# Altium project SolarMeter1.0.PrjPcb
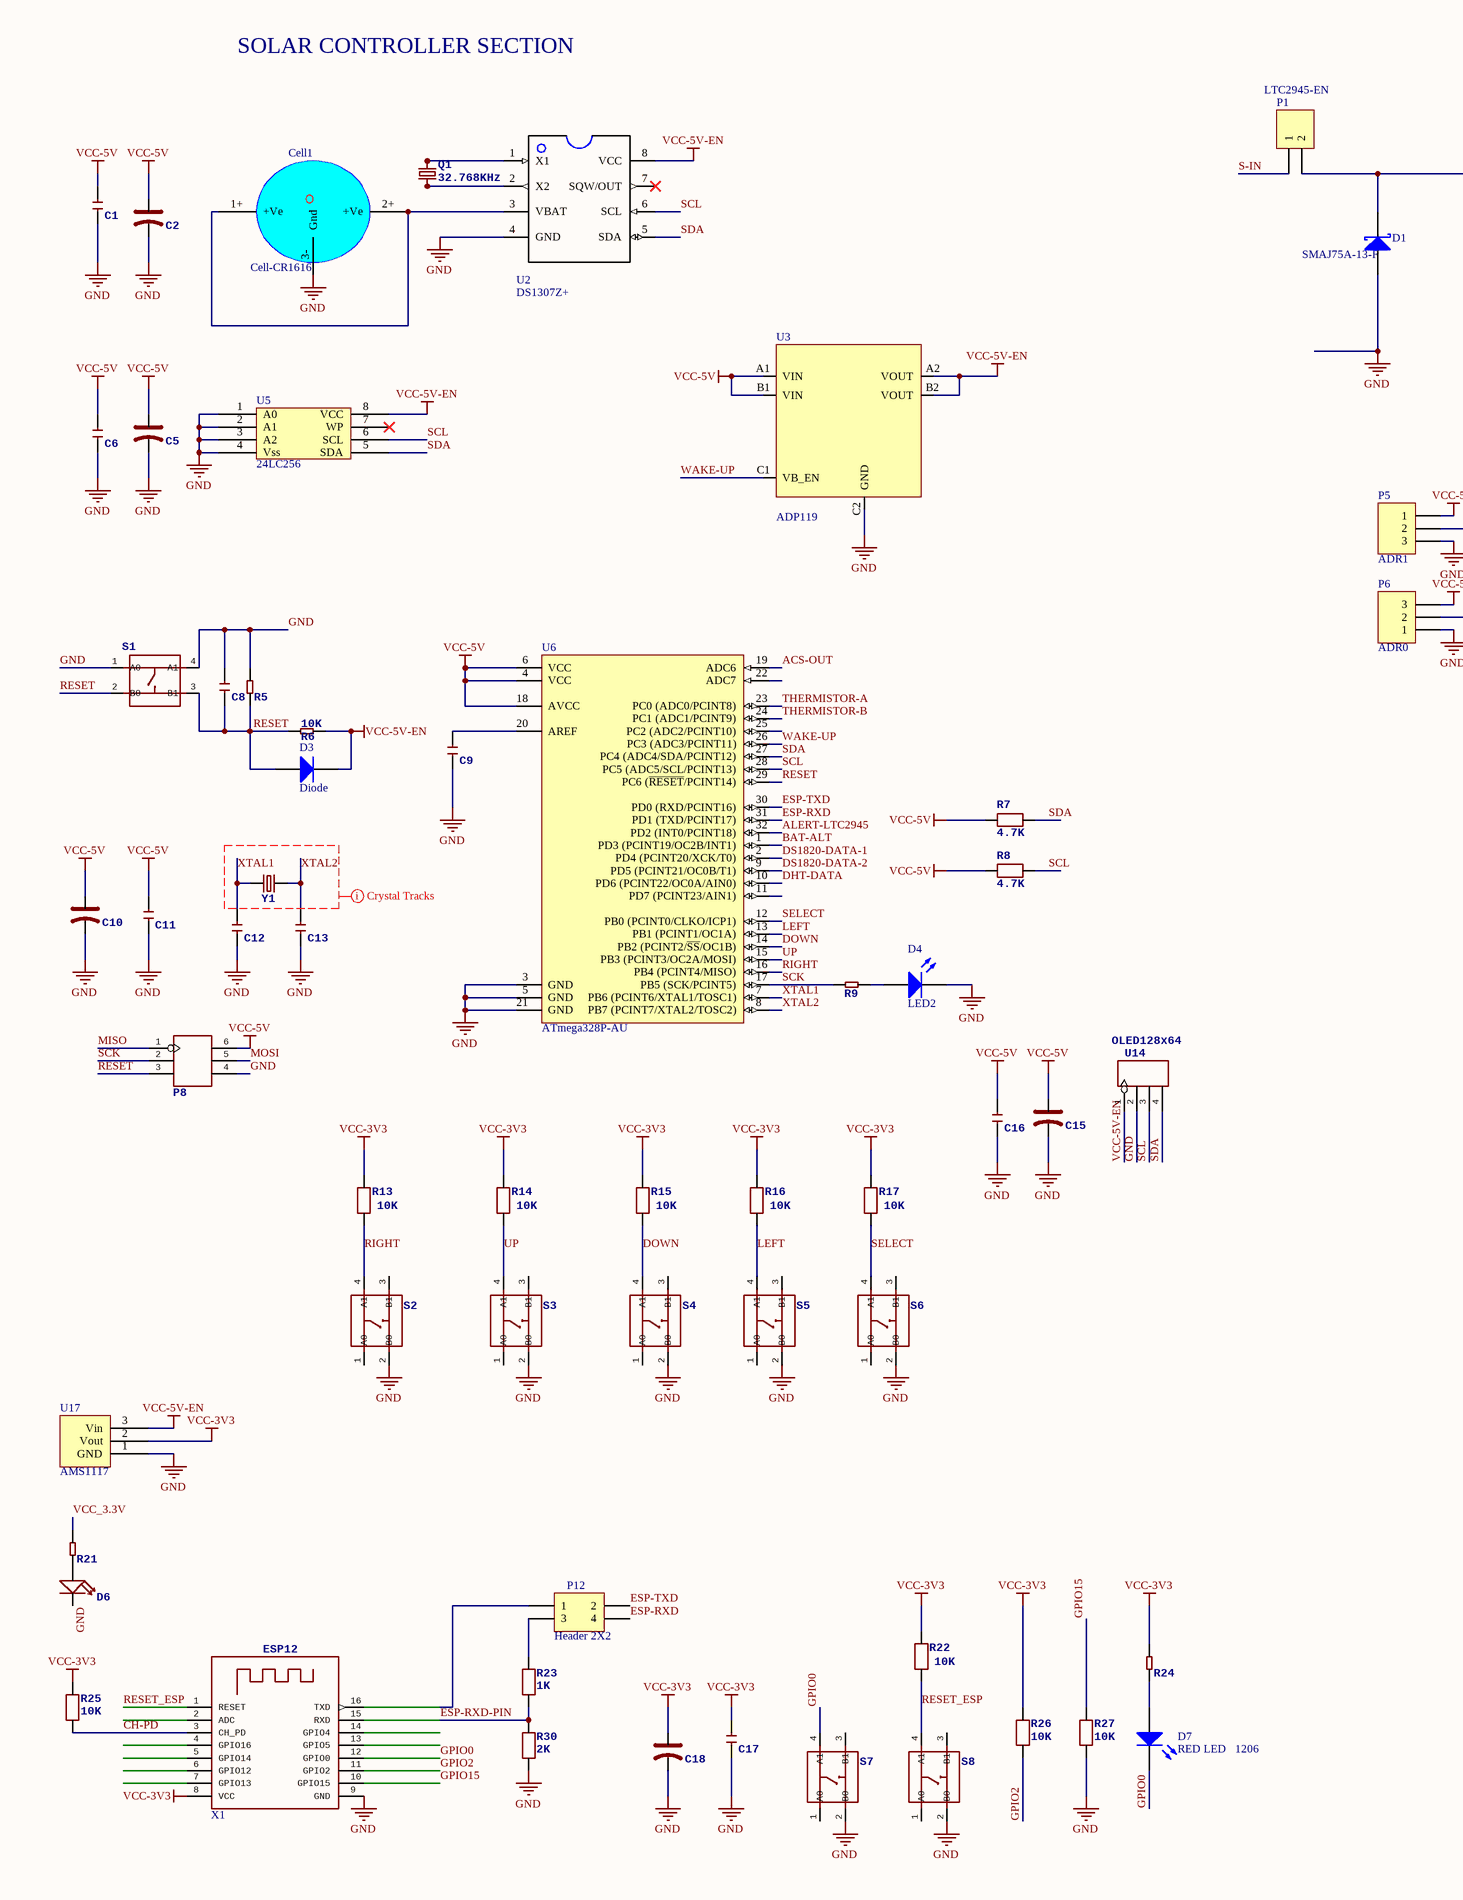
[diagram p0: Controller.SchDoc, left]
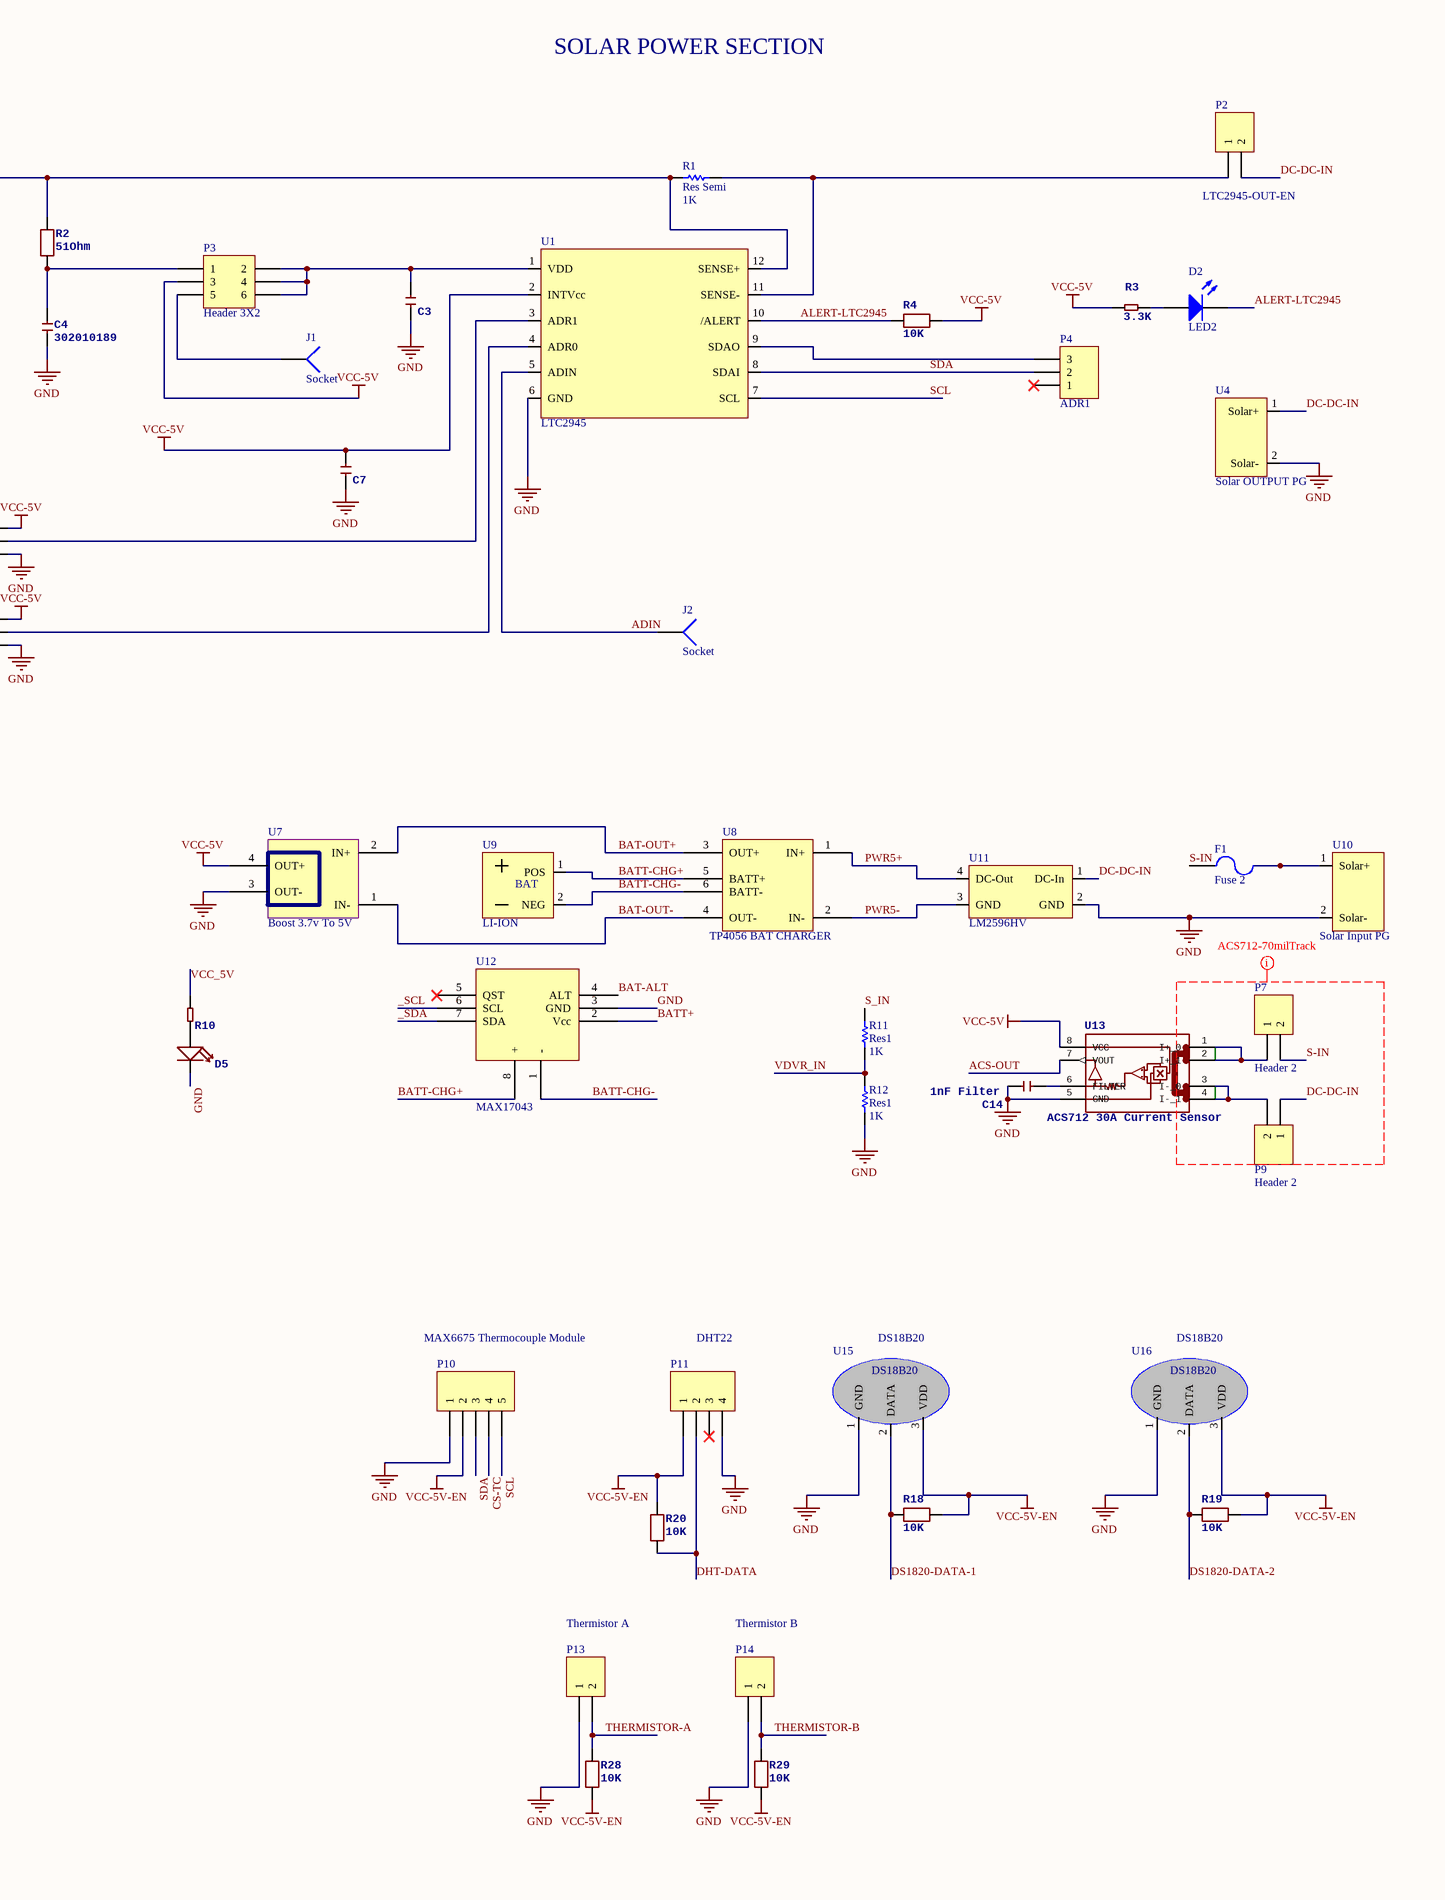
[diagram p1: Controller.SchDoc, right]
1 sheet, 101 parts. Net scope: global (net labels, ports and power ports of the same name join across sheets).
Board file: SolarMetering1.0.PcbDoc

## Sheet Controller.SchDoc: Solar Monitoring 1.0
size A2

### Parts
C1  302010165  [C0805]  (value not drawn)
C2  302020002  [AVX-A]  (value not drawn)
C3  302010165  [C0805]  (value not drawn)
C4  302010189  [C1206]
C5  302020002  [AVX-A]  (value not drawn)
C6  302010165  [C0805]  (value not drawn)
C7  302010165  [C0805]  (value not drawn)
C8  302010165  [C0805]  (value not drawn)
C9  302010165  [C0805]  (value not drawn)
C10  302020002  [AVX-A]  (value not drawn)
C11  302010165  [C0805]  (value not drawn)
C12  302010018  [C0805]  (value not drawn)
C13  302010018  [C0805]  (value not drawn)
C14  1nF Filter  [C0805]
C15  302020002  [AVX-A]  (value not drawn)
C16  302010165  [C0805]  (value not drawn)
C17  302010165  [C0805]  (value not drawn)
C18  302020002  [AVX-A]  (value not drawn)
Cell1  Cell-CR1616  [CellCR1616]
D1  SMAJ75A-13-F  [SMAJ5.0-TVS]
D2  LED2  [3.2X1.6X1.1]
D3  Diode  [1206 Diode SMD]
D4  LED2  [3.2X1.6X1.1]
D5  304090046  [LED-0805]  (value not drawn)
D6  304090045  [LED-0603]  (value not drawn)
D7  RED LED   1206  [3.2X1.6X1.1]
F1  Fuse 2  [PIN-W2/E2.8]
J1  Socket  [PIN1]
J2  Socket  [PIN1]
P1  LTC2945-EN  [HDR1X2]
P2  LTC2945-OUT-EN  [HDR1X2]
P3  Header 3X2  [HDR2X3]
P4  ADR1  [HDR1X3]
P5  ADR1  [HDR1X3]
P6  ADR0  [HDR1X3]
P7  Header 2  [HDR1X2]
P8  320020077  [HDR1X6]  (value not drawn)
P9  Header 2  [HDR1X2]
P10  MAX6675 Thermocouple Module  [HDR1X5]
P11  DHT22  [HDR1X4]
P12  Header 2X2  [HDR2X2]
P13  Thermistor A  [HDR1X2]
P14  Thermistor B  [HDR1X2]
Q1  32.768KHz  [RTC-XTAL]
R1  Res Semi  value 1K  [AXIAL-0.5]
R2  51Ohm  [R0805]
R3  3.3K  [C1206]
R4  10K  [R0805]
R5  301010006  [R0402]  (value not drawn)
R6  10K  [R0805]
R7  4.7K  [R0805]
R8  4.7K  [R0805]
R9  301010466  [C1206]  (value not drawn)
R10  301010006  [R0402]  (value not drawn)
R11  Res1  value 1K  [AXIAL-0.3]
R12  Res1  value 1K  [AXIAL-0.3]
R13  10K  [R0805]
R14  10K  [R0805]
R15  10K  [R0805]
R16  10K  [R0805]
R17  10K  [R0805]
R18  10K  [R0805]
R19  10K  [R0805]
R20  10K  [R0805]
R21  301010006  [R0402]  (value not drawn)
R22  10K  [R0805]
R23  1K  [R0805]
R24  1K  [C1206]  (value not drawn)
R25  10K  [R0805]
R26  10K  [R0805]
R27  10K  [R0805]
R28  10K  [R0805]
R29  10K  [R0805]
R30  2K  [R0805]
S1  311020004  [SW4-SMD-6.0X6.0X5.0MM]  (value not drawn)
S2  311020004  [SW4-SMD-6.0X6.0X5.0MM]  (value not drawn)
S3  311020004  [SW4-SMD-6.0X6.0X5.0MM]  (value not drawn)
S4  311020004  [SW4-SMD-6.0X6.0X5.0MM]  (value not drawn)
S5  311020004  [SW4-SMD-6.0X6.0X5.0MM]  (value not drawn)
S6  311020004  [SW4-SMD-6.0X6.0X5.0MM]  (value not drawn)
S7  311020004  [SW4-SMD-6.0X6.0X5.0MM]  (value not drawn)
S8  311020004  [SW4-SMD-6.0X6.0X5.0MM]  (value not drawn)
U1  LTC2945  [LTC2945]
U2  DS1307Z+  [SO08]
U3  ADP119  [BGA3x2]
U4  Solar OUTPUT PG  [SCREW TERMINAL]
U5  24LC256  [SO08]
U6  ATmega328P-AU  [TQFP32-0.8-7X7MM]
U7  Boost 3.7v To 5V  [PowerOut]
U8  TP4056 BAT CHARGER  [TP4056]
U9  LI-ION  [H2-2.54]
U10  Solar Input PG  [SCREW TERMINAL]
U11  LM2596HV  [LM2596HVS DC-DC step-down module]
U12  MAX17043  [MAX17043]
U13  ACS712 30A Current Sensor  [SO08]
U14  OLED128x64  [H4-2.54]
U15  DS18B20  [TO-92]
U16  DS18B20  [TO-92]
U17  AMS1117  [AMS1117-3.3]
X1  ESP-12  [ESP8266-12E]  (value not drawn)
Y1  306010054  [SMT_XTAL]  (value not drawn)

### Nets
GND: C1.1 C2.- C3.1 C4.1 C5.- C6.1 C7.1 C8.2 C9.1 C10.- C11.1 C12.1 C13.1 C14.1 C15.- C16.1 C17.1 C18.- Cell1.3-(Gnd) D1.1(A) D4.2(K) D5.- D6.- P5.3 P6.1 P8.4 P10.1 P11.4 P13.1 P14.1 R5.1 R12.1 R27.1 R30.1 S1.1(A0) S1.4(A1) S2.2(B0) S3.2(B0) S4.2(B0) S5.2(B0) S6.2(B0) S7.2(B0) S8.2(B0) U1.6(GND) U2.4(GND) U3.C2(GND) U4.2(Solar-) U5.1(A0) U5.2(A1) U5.3(A2) U5.4(Vss) U6.3(GND) U6.5(GND) U6.21(GND) U7.3(OUT-) U10.2(Solar-) U11.2(GND) U12.3(GND) U13.5(GND) U14.2(P$2) U15.1(GND) U16.1(GND) U17.1(GND) X1.9(GND)
VCC-3V3: C17.2 C18.+ R13.2 R14.2 R15.2 R16.2 R17.2 R22.2 R24.1 R25.2 R26.2 U17.2(Vout) X1.8(VCC)
VCC-5V: C1.2 C2.+ C5.+ C6.2 C7.2 C10.+ C11.2 C15.+ C16.2 P3.3 P5.1 P6.3 P8.6 R3.1 R4.2 R7.2 R8.2 U1.2(INTVcc) U3.A1(VIN) U3.B1(VIN) U6.4(VCC) U6.6(VCC) U6.18(AVCC) U7.4(OUT+) U13.8(VCC)
VCC-5V-EN: D3.2(K) P10.2 P11.1 R6.2 R18.1 R19.1 R20.2 R28.1 R29.1 U2.8(VCC) U3.A2(VOUT) U3.B2(VOUT) U5.8(VCC) U14.1(P$1) U15.3(VDD) U16.3(VDD) U17.3(Vin)
_SCL: U12.6(SCL)
_SDA: U12.7(SDA)
ACS-OUT: U6.19(ADC6) U13.7(VOUT)
ADIN: J2.1 U1.5(ADIN)
ALERT-LTC2945: D2.2(K) R4.1 U1.10(/ALERT) U6.32(PD2_(INT0/PCINT18))
BAT-ALT: U6.1(PD3_(PCINT19/OC2B/INT1)) U12.4(ALT)
BAT-OUT+: U7.2(IN+) U8.3(OUT+)
BAT-OUT-: U7.1(IN-) U8.4(OUT-)
BATT+: U12.2(Vcc)
BATT-CHG+: U8.5(BATT+) U9.1(POS) U12.8(+)
BATT-CHG-: U8.6(BATT-) U9.2(NEG) U12.1(-)
CH-PD: R25.1 X1.3(CH_PD)
CS-TC: P10.4
DC-DC-IN: P2.2 P9.1 U4.1(Solar+) U11.1(DC-In)
DHT-DATA: P11.2 R20.1 U6.10(PD6_(PCINT22/OC0A/AIN0))
DOWN: R15.1 S4.4(A1) U6.14(PB2_(PCINT2/~{SS}/OC1B))
DS1820-DATA-1: R18.2 U6.2(PD4_(PCINT20/XCK/T0)) U15.2(DATA)
DS1820-DATA-2: R19.2 U6.9(PD5_(PCINT21/OC0B/T1)) U16.2(DATA)
ESP-RXD: P12.4 U6.31(PD1_(TXD/PCINT17))
ESP-RXD-PIN: R23.1 R30.2 X1.15(RXD)
ESP-TXD: P12.2 U6.30(PD0_(RXD/PCINT16))
GPIO0: D7.2(K) S7.4(A1) X1.12(GPIO0)
GPIO2: R26.1 X1.11(GPIO2)
GPIO15: R27.2 X1.10(GPIO15)
LEFT: R16.1 S5.4(A1) U6.13(PB1_(PCINT1/OC1A))
MISO: P8.1
MOSI: P8.5
PWR5+: U8.1(IN+) U11.4(DC-Out)
PWR5-: U8.2(IN-) U11.3(GND)
RESET: C8.1 D3.1(A) P8.3 R5.2 R6.1 S1.2(B0) S1.3(B1) U6.29(PC6_(~{RESET}/PCINT14))
RESET_ESP: R22.1 S8.4(A1) X1.1(RESET)
RIGHT: R13.1 S2.4(A1) U6.16(PB4_(PCINT4/MISO))
S-IN: F1.1 P1.1 P7.2
S_IN: R11.2
SCK: P8.2 R9.1 U6.17(PB5_(SCK/PCINT5))
SCL: P10.5 R8.1 U1.7(SCL) U2.6(SCL) U5.6(SCL) U6.28(PC5_(ADC5/SCL/PCINT13)) U14.3(P$3)
SDA: P4.2 P10.3 R7.1 U1.8(SDAI) U2.5(SDA) U5.5(SDA) U6.27(PC4_(ADC4/SDA/PCINT12)) U14.4(P$4)
SELECT: R17.1 S6.4(A1) U6.12(PB0_(PCINT0/CLKO/ICP1))
THERMISTOR-A: P13.2 R28.2 U6.23(PC0_(ADC0/PCINT8))
THERMISTOR-B: P14.2 R29.2 U6.24(PC1_(ADC1/PCINT9))
UP: R14.1 S3.4(A1) U6.15(PB3_(PCINT3/OC2A/MOSI))
VCC_3.3V: R21.1
VCC_5V: R10.1
VDVR_IN: R11.1 R12.2
WAKE-UP: U3.C1(VB_EN) U6.26(PC3_(ADC3/PCINT11))
XTAL1: C12.2 U6.7(PB6_(PCINT6/XTAL1/TOSC1)) Y1.1
XTAL2: C13.2 U6.8(PB7_(PCINT7/XTAL2/TOSC2)) Y1.2
NetC3_2: C3.2 P3.2 P3.4 P3.6 U1.1(VDD)
NetC4_2: C4.2 P3.1 R2.2
NetC9_2: C9.2 U6.20(AREF)
NetC14_2: C14.2 U13.6(FILTER)
NetCell1_1+: Cell1.1+(+Ve) Cell1.2+(+Ve) U2.3(VBAT)
NetD1_2: D1.2(K) P1.2 R1.1 R2.1 U1.12(SENSE+)
NetD2_1: D2.1(A) R3.2
NetD4_1: D4.1(A) R9.2
NetD5_+: D5.+ R10.2
NetD6_+: D6.+ R21.2
NetD7_1: D7.1(A) R24.2
NetF1_2: F1.2 U10.1(Solar+)
NetJ1_1: J1.1 P3.5
NetP2_1: P2.1 R1.2 U1.11(SENSE-)
NetP4_3: P4.3 U1.9(SDAO)
NetP5_2: P5.2 U1.3(ADR1)
NetP6_2: P6.2 U1.4(ADR0)
NetP7_1: P7.1 U13.1(I+_0) U13.2(I+_1)
NetP9_2: P9.2 U13.3(I-_0) U13.4(I-_1)
NetP12_1: P12.1 X1.16(TXD)
NetP12_3: P12.3 R23.2
NetQ1_1: Q1.1 U2.1(X1)
NetQ1_2: Q1.2 U2.2(X2)

Not connected (* = marked no-connect by the designer): P4 1*; P11 3*; S2 1(A0) 3(B1); S3 1(A0) 3(B1); S4 1(A0) 3(B1); S5 1(A0) 3(B1); S6 1(A0) 3(B1); S7 1(A0) 3(B1); S8 1(A0) 3(B1); U2 7(SQW/OUT)*; U5 7(WP)*; U6 11(PD7_(PCINT23/AIN1)) 22(ADC7) 25(PC2_(ADC2/PCINT10)); U12 5(QST)*; X1 2(ADC) 4(GPIO16) 5(GPIO14) 6(GPIO12) 7(GPIO13) 13(GPIO5) 14(GPIO4)

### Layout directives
rule Routing Layers [TopLayer - Enabled BottomLayer - Disabled]: XTAL1, XTAL2
ACS712-70milTrackIN: ACS712-70milTrack; rule Width Constraint [Pref Width = 70mil    Min Width = 70mil    Max Width = 70mil]: DC-DC-IN, S-IN

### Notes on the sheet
- SOLAR CONTROLLER SECTION
- SOLAR POWER SECTION

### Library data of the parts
C1 C3 C6-C9 C11 C16 C17 = CERAMIC-100NF-50V-10%-X7R(0805): 100nF; MPN: CC0805KRX7R9BB104
C2 C5 C10 C15 C18 = TANTALUM-SMD-10UF-16V-10%(AVX-A): 10uF Cap Decoupling 16V; MPN: TAJA106K016RNJ
C4 = CERAMIC-1NF-1KV-10%-X7R?(1206): MPN: CC1206KKX7RCBB102
C12 C13 = CERAMIC-22PF-50V-5%-NPO(0402): MPN: CC0402JRNPO9BN220
C14 = CERAMIC-100NF-25V-10%-X7R(0402): 1nF Filter Cap as per Datasheet; MPN: CC0402KRX7R8BB104
D1 = D Schottky: SMA
D2 D4 D7 = LED2: Typical RED, GREEN, YELLOW, AMBER GaAs LED
D3 = Diode: Default Diode
D5 = SMD-LED-CLEAR-RED(0805): MPN: 17-215SURC/S530-A2/TR8
D6 = SMD-LED-CLEAR-BLUE(0603): MPN: 19-217-BHC-ZL1M2RY-3T
F1 = Fuse 2: Fuse
P1 P2 P7 P9 P13 P14 = Header 2: Header, 2-Pin
P3 = Header 3X2: Header, 3-Pin, Dual row
P4-P6 = Header 3: Header, 3-Pin
P8 = DIP-BLACK-MALE-HEADER(2X3P-2.54）-2.54: MPN: P125-12A1BS116A1
P10 = Header 5: Header, 5-Pin
P11 = Header 4: Header, 4-Pin
P12 = Header 2X2: Header, 2-Pin, Dual row
Q1 = CRYTALTC38H
R1 = Res Semi: Semiconductor Resistor
R2 R4 R7 R8 R13-R20 R22 R23 R25-R30 = RESISTOR0805_NOOUTLINE: Resistors   For new designs, use the packages preceded by an '_' character since they are more reliable:   The following footprints should be used on most boards: _0402 - Standard footprint for regular board layouts  _0603 - Standard footprint for regular board layouts  _0805 - Standard footprint for regular board layouts  _1206 - Standard footprint for regular board layouts       For extremely tight-pitch boards where space is at a premium, the following 'micro-pitch' footprints can be used (smaller pads, no silkscreen outline, etc.): _0402MP - Micro-pitch footprint for very dense/compact boards  _0603MP - Micro-pitch footprint for very dense/compact boards  _0805MP - Micro-pitch footprint for very dense/compact boards  _1206MP - Micro-pitch footprint for very dense/compact boards
R3 R9 = SMD-RES-330R-1%-1/16W(0402): MPN: RC0402FR-07330RL
R5 R6 R10 R21 = SMD-RES-1K-5%-1/16W(0402): MPN: RC0402JR-071KL
R11 R12 = Res1: Resistor
R24 = SMD-RES-330R-1%-1/16W(0402): 1K 1206; MPN: RC0402FR-07330RL
S1-S8 = SMD-SWITCH-TACTILE-SPST-NO(4P-D6.0MM): MPN: DTSM-62K-S-V-T/R(SN431)
U1 = LTC2945: V I P Monitor I2C Interface
U2 = DS1307Z+: RTC circuit%3B I2C%3B NV SRAM%3B 56B%3B 4.5%C3%B75.5VDC%3B SO8; MF: Maxim Integrated
U4 U10 = PG_IN
U6 = ATmega328P-AU: 8-bit AVR Microcontroller, 32KB Flash, 1KB EEPROM, 2KB SRAM, 32-pin TQFP, Industrial Grade (-40°C to 85°C)
U7 = PowerOut Module: USB Power Out module
U8 = TP4056: TP4056 Module
U9 = Battery: Li Ion Battery 3.7V
U11 = LM2596HV: DC DC Adjustable Buck converter input upto 60V
U12 = MAX17043: Battery Fuel Guage
U13 = ACS712
U14 = DIP-BLACK-MALE-HEADER-VERT(4P-2.54): MPN: P125-1104A0BS116A1
U15 U16 = DS18B20: On Board Temperature Sensor
U17 = AMS1117: 3.3V Regulator
Y1 = SMD-CRYSTAL-16MHZ-8PF-20PPM-40R(2P-5.0X3.2MM): MPN: X053201602002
